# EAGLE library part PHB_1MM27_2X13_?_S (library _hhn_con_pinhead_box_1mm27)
Pin Header Box-Type, 1.27mm/0.5"/50mil Pitch, 2x12 Circuits, single gates in schematic Note: see library description for an important note about THT-version
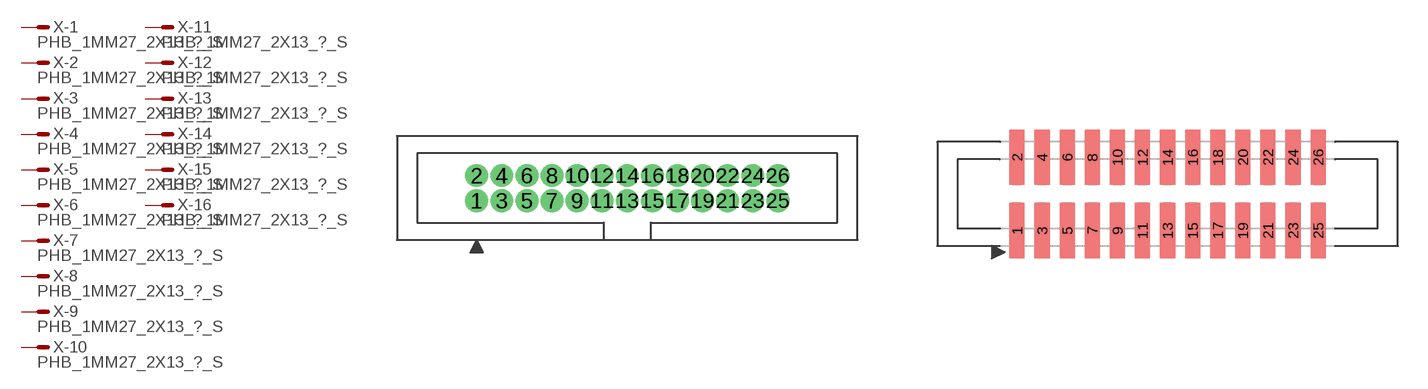
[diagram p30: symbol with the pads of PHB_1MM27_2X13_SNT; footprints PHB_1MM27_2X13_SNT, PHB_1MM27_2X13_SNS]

Designator prefix X; gates -1=M -2=M -3=M -4=M -5=M -6=M -7=M -8=M -9=M -10=M -11=M -12=M -13=M -14=M -15=M -16=M -17=M -18=M -19=M -20=M -21=M -22=M -23=M -24=M -25=M -26=M

## PHB_1MM27_2X13_SNT_S  [PHB_1MM27_2X13_SNT]
1  -1:S  pas
2  -2:S  pas
3  -3:S  pas
4  -4:S  pas
5  -5:S  pas
6  -6:S  pas
7  -7:S  pas
8  -8:S  pas
9  -9:S  pas
10  -10:S  pas
11  -11:S  pas
12  -12:S  pas
13  -13:S  pas
14  -14:S  pas
15  -15:S  pas
16  -16:S  pas
17  -17:S  pas
18  -18:S  pas
19  -19:S  pas
20  -20:S  pas
21  -21:S  pas
22  -22:S  pas
23  -23:S  pas
24  -24:S  pas
25  -25:S  pas
26  -26:S  pas

## PHB_1MM27_2X13_SNS_S  [PHB_1MM27_2X13_SNS]
Pads as for PHB_1MM27_2X13_SNT

## Footprint PHB_1MM27_2X13_SNT (pad centres in mm)
Pin Header Box-Type, 1.27mm Pitch, 2x13 circuits, Straight, No Locking, THT Important Note: Diameter in this lbr is set to a specific value (NOT 'auto' = 0), this is ignored by actual eagle versions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
drill 0.65 pad 1 round: 1 -7.62,-0.635; 2 -7.62,0.635; 3 -6.35,-0.635; 4 -6.35,0.635; 5 -5.08,-0.635; 6 -5.08,0.635; 7 -3.81,-0.635; 8 -3.81,0.635; 9 -2.54,-0.635; 10 -2.54,0.635; 11 -1.27,-0.635; 12 -1.27,0.635; 13 0,-0.635; 14 0,0.635; 15 1.27,-0.635; 16 1.27,0.635; 17 2.54,-0.635; 18 2.54,0.635; 19 3.81,-0.635; 20 3.81,0.635; 21 5.08,-0.635; 22 5.08,0.635; 23 6.35,-0.635; 24 6.35,0.635; 25 7.62,-0.635; 26 7.62,0.635

## Footprint PHB_1MM27_2X13_SNS (pad centres in mm)
Pin Header Box-Type, 1.27mm Pitch, 2x13 circuits, Straight, No Locking, SMT
smd 0.76 x 2.8: 1 -7.62,-1.85; 2 -7.62,1.85; 3 -6.35,-1.85; 4 -6.35,1.85; 5 -5.08,-1.85; 6 -5.08,1.85; 7 -3.81,-1.85; 8 -3.81,1.85; 9 -2.54,-1.85; 10 -2.54,1.85; 11 -1.27,-1.85; 12 -1.27,1.85; 13 0,-1.85; 14 0,1.85; 15 1.27,-1.85; 16 1.27,1.85; 17 2.54,-1.85; 18 2.54,1.85; 19 3.81,-1.85; 20 3.81,1.85; 21 5.08,-1.85; 22 5.08,1.85; 23 6.35,-1.85; 24 6.35,1.85; 25 7.62,-1.85; 26 7.62,1.85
